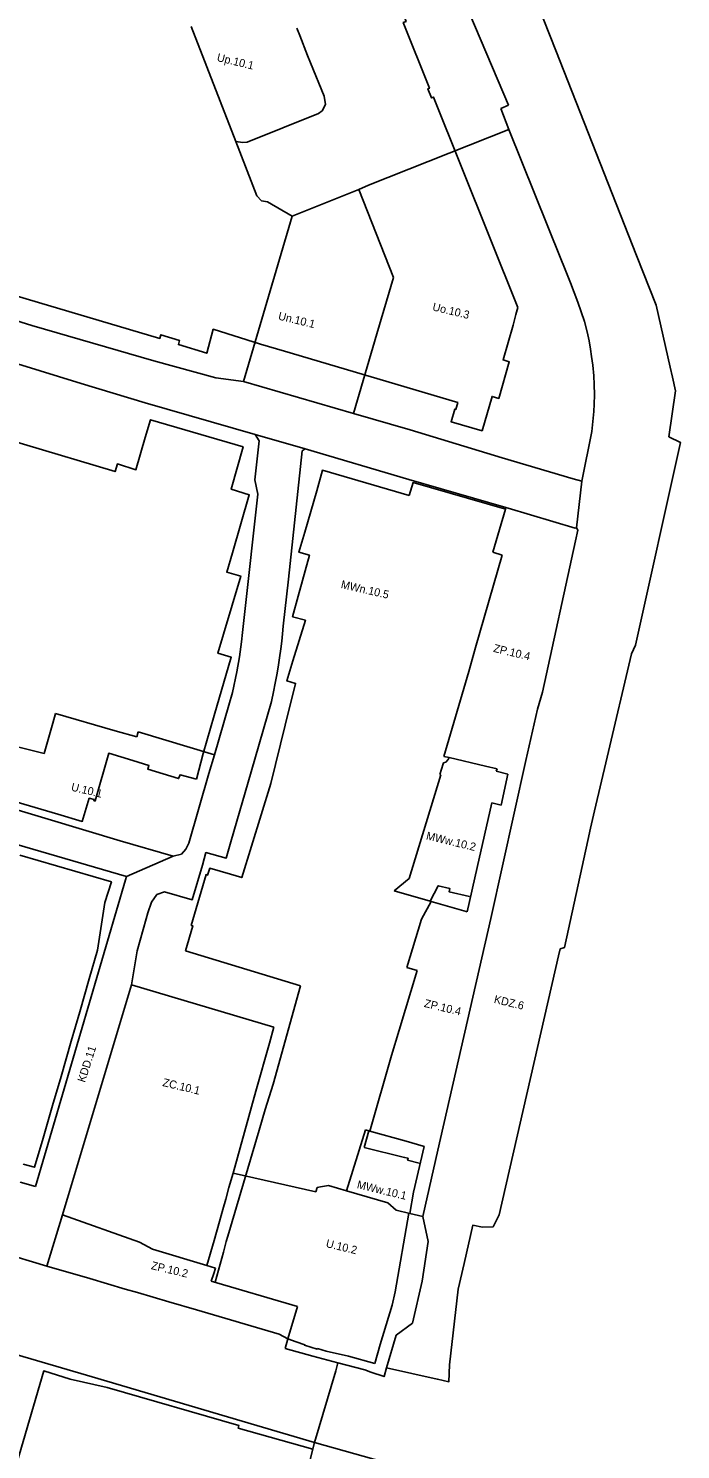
# Model space of a CAD drawing. Extents: x 7429686 to 7432896, y 5547954 to 5550600.
# Drawn here: x 7431990 to 7432316, y 5548459 to 5549170 of the extents above; entities that cross this region are included whole.
import ezdxf

# ---------------------------------------------------------------- set-up
doc = ezdxf.new("R2010")
doc.units = 0
for name, color, linetype in [('granica planu', 7, 'Continuous'), ('linie rozgraniczające', 7, 'Continuous'), ('nieprzekraczalna linia zabudowy', 7, 'Continuous'), ('obowiązująca linia zabudowy', 7, 'Continuous'), ('oznaczenia przeznaczeń', 7, 'Continuous')]:
    doc.layers.add(name, color=color, linetype=linetype)

msp = doc.modelspace()

# ---------------------------------------------------------------- linework, layer by layer
at = {"layer": 'granica planu'}
for points in [[(7432203.11, 5549285.85), (7432253.35, 5549158.49), (7432293.8, 5549055.97), (7432303.59, 5549031.15), (7432310.64, 5549000.22), (7432311.77, 5548995.18), (7432313.3, 5548988.36), (7432309.98, 5548965.44), (7432315.78, 5548962.55), (7432293.25, 5548861.19), (7432291.27, 5548856.84), (7432279.1, 5548805.19), (7432272.8, 5548778.46), (7432270.7, 5548769.64), (7432269.38, 5548763.55), (7432257.74, 5548710.02), (7432255.6, 5548709.36), (7432254.81, 5548705.91), (7432225.08, 5548576.47), (7432222.05, 5548570.38), (7432216.81, 5548570.26), (7432211.93, 5548571.17), (7432207.55, 5548552.09), (7432204.59, 5548539.19), (7432200.26, 5548501.41), (7432200, 5548492.94)], [(7432200, 5548492.94), (7432194.33, 5548494.21), (7432194.14, 5548494.25), (7432168.86, 5548499.89), (7432167.55, 5548495.53), (7432161.04, 5548497.78), (7432158.03, 5548498.87), (7432144.51, 5548502.39), (7432143.43, 5548498.33), (7432132.81, 5548462.54), (7432162.54, 5548454.18), (7432165.08, 5548453.77), (7432164.94, 5548451.89), (7432168.88, 5548447.76), (7432167.65, 5548438.77), (7432180.47, 5548435.15), (7432182.05, 5548445.83)]]:
    msp.add_lwpolyline(points, dxfattribs=at)
at = {"layer": 'linie rozgraniczające'}
for points in [[(7432168.86, 5548499.89), (7432194.14, 5548494.25), (7432194.33, 5548494.21), (7432200, 5548492.94), (7432200.26, 5548501.41), (7432204.59, 5548539.19), (7432207.55, 5548552.09), (7432211.93, 5548571.17), (7432216.81, 5548570.26), (7432222.05, 5548570.38), (7432225.08, 5548576.47), (7432254.81, 5548705.91), (7432255.6, 5548709.36), (7432257.74, 5548710.02), (7432269.38, 5548763.55), (7432270.7, 5548769.64), (7432272.8, 5548778.46), (7432279.1, 5548805.19), (7432291.27, 5548856.84), (7432293.25, 5548861.19), (7432315.78, 5548962.55), (7432309.98, 5548965.44), (7432313.3, 5548988.36), (7432311.77, 5548995.18), (7432310.64, 5549000.22), (7432303.59, 5549031.15), (7432293.8, 5549055.97), (7432253.35, 5549158.49), (7432203.11, 5549285.85)], [(7432229.83, 5549131.2), (7432207.69, 5549183.3)], [(7432093.48, 5549113.01), (7432071.12, 5549170.55)], [(7432124.05, 5549169.74), (7432125.48, 5549166.09)], [(7432125.48, 5549166.09), (7432129.3, 5549156.12)], [(7432129.3, 5549156.12), (7432130.75, 5549152.41)], [(7432130.75, 5549152.41), (7432137.69, 5549135.71)], [(7432137.69, 5549135.71), (7432138.38, 5549131.58)], [(7432134.86, 5549126.97), (7432099.15, 5549112.79)], [(7432136.66, 5549128.33), (7432134.86, 5549126.97)], [(7432138.38, 5549131.58), (7432136.66, 5549128.33)], [(7432225.87, 5549129.6), (7432229.83, 5549131.2)], [(7432230.02, 5549119.08), (7432225.87, 5549129.6)], [(7432159.78, 5549091.18), (7432230.02, 5549119.08)], [(7432255.91, 5549054.43), (7432230.02, 5549119.08)], [(7432104.03, 5549085.85), (7432093.48, 5549113.01)], [(7432096.91, 5549112.48), (7432093.48, 5549113.01)], [(7432099.15, 5549112.79), (7432096.91, 5549112.48)], [(7432154.96, 5549089.12), (7432159.78, 5549091.18)], [(7432106.29, 5549083.34), (7432104.03, 5549085.85)], [(7432109.26, 5549082.81), (7432106.29, 5549083.34)], [(7432121.67, 5549075.7), (7432109.26, 5549082.81)], [(7432121.67, 5549075.7), (7432154.96, 5549089.12)], [(7432172.23, 5549045.13), (7432154.96, 5549089.12)], [(7432108.98, 5549032.73), (7432121.67, 5549075.7)], [(7432257.76, 5549049.82), (7432255.91, 5549054.43)], [(7432260.77, 5549042.31), (7432257.76, 5549049.82)], [(7432164, 5549016.82), (7432172.23, 5549045.13)], [(7432264.5, 5549032.64), (7432260.77, 5549042.31)], [(7431991.53, 5549021.11), (7431973.2, 5549026.64)], [(7432097.35, 5548993.11), (7432108.98, 5549032.73)], [(7432267.76, 5549023.05), (7432264.5, 5549032.64)], [(7432052.51, 5549003.41), (7431991.53, 5549021.11)], [(7432269.08, 5549017.85), (7432267.76, 5549023.05)], [(7432152.22, 5548977.04), (7432164, 5549016.82)], [(7432270.06, 5549013.43), (7432269.08, 5549017.85)], [(7432270.84, 5549009.14), (7432270.06, 5549013.43)], [(7432271.31, 5549005.52), (7432270.84, 5549009.14)], [(7432271.9, 5549001.19), (7432271.31, 5549005.52)], [(7431984.36, 5549001.84), (7432016.11, 5548992.11)], [(7432083.44, 5548994.94), (7432052.51, 5549003.41)], [(7432272.37, 5548995.94), (7432271.9, 5549001.19)], [(7432016.11, 5548992.11), (7432048.11, 5548982.42)], [(7432097.35, 5548993.11), (7432083.44, 5548994.94)], [(7432152.22, 5548977.04), (7432097.35, 5548993.11)], [(7432272.66, 5548991.47), (7432272.37, 5548995.94)], [(7432272.75, 5548986.4), (7432272.66, 5548991.47)], [(7432272.66, 5548981.78), (7432272.75, 5548986.4)], [(7432048.11, 5548982.42), (7432103.12, 5548966.63)], [(7432180.66, 5548968.86), (7432152.22, 5548977.04)], [(7432271.91, 5548973.09), (7432272.39, 5548978.03)], [(7432272.39, 5548978.03), (7432272.66, 5548981.78)], [(7432271.47, 5548968.1), (7432271.91, 5548973.09)], [(7432103.01, 5548943.88), (7432105.13, 5548963.38)], [(7432103.12, 5548966.63), (7432128.2, 5548959.36)], [(7432105.13, 5548963.38), (7432103.12, 5548966.63)], [(7432226.68, 5548954.9), (7432180.66, 5548968.86)], [(7432266.39, 5548943.16), (7432271.47, 5548968.1)], [(7432128.2, 5548959.36), (7432126.61, 5548958.33), (7432119.75, 5548894.25), (7432117.22, 5548870.67), (7432116.81, 5548866.89), (7432116.44, 5548863.14), (7432116.01, 5548859.37), (7432115.37, 5548854.86), (7432114.64, 5548850.29), (7432113.97, 5548846.38), (7432113.21, 5548842.27), (7432112.27, 5548837.86), (7432111.24, 5548833.11), (7432101.1, 5548797.96), (7432090.96, 5548762.83), (7432088.73, 5548754.77), (7432078.54, 5548757.51), (7432076.77, 5548751.25), (7432071.7, 5548733.94), (7432057.91, 5548737.91), (7432054.07, 5548736.6), (7432051.26, 5548732.71), (7432049.55, 5548727.35), (7432048.68, 5548724.33), (7432044.15, 5548708.4), (7432041.39, 5548691.31)], [(7432128.2, 5548959.36), (7432179.92, 5548944.13)], [(7432262.04, 5548944.46), (7432226.68, 5548954.9)], [(7432104.41, 5548936.74), (7432103.01, 5548943.88)], [(7432179.92, 5548944.13), (7432228.44, 5548930.02)], [(7432266.39, 5548943.16), (7432262.04, 5548944.46)], [(7432263.68, 5548919.85), (7432266.39, 5548943.16)], [(7432097.86, 5548876.55), (7432104.41, 5548936.74)], [(7432225.27, 5548919.02), (7432228.21, 5548929.2)], [(7432228.21, 5548929.2), (7432228.44, 5548930.02)], [(7432228.44, 5548930.02), (7432229.57, 5548929.69)], [(7432229.57, 5548929.69), (7432263.04, 5548919.68)], [(7432263.04, 5548919.68), (7432263.68, 5548919.85)], [(7432264.44, 5548918.78), (7432263.68, 5548919.85)], [(7432221.99, 5548907.67), (7432225.27, 5548919.02)], [(7432246.79, 5548837.75), (7432263.3, 5548913.34)], [(7432263.3, 5548913.34), (7432264.44, 5548918.78)], [(7432213.35, 5548860.03), (7432226.56, 5548906.19)], [(7432226.56, 5548906.19), (7432221.99, 5548907.67)], [(7432096.88, 5548867.48), (7432097.36, 5548872.04)], [(7432097.36, 5548872.04), (7432097.86, 5548876.55)], [(7432095.31, 5548855.46), (7432096.35, 5548862.95)], [(7432096.35, 5548862.95), (7432096.88, 5548867.48)], [(7432093.97, 5548847.96), (7432095.31, 5548855.46)], [(7432209.94, 5548847.99), (7432213.35, 5548860.03)], [(7432091.75, 5548837.62), (7432093.97, 5548847.96)], [(7432197.42, 5548805.62), (7432209.94, 5548847.99)], [(7432089.92, 5548831.17), (7432091.75, 5548837.62)], [(7432244.25, 5548829.15), (7432246.79, 5548837.75)], [(7432001.98, 5548822.29), (7432003.3, 5548827.01)], [(7432003.3, 5548827.01), (7432033.19, 5548818.44)], [(7432082.76, 5548806.4), (7432089.92, 5548831.17)], [(7432238.52, 5548803.54), (7432244.25, 5548829.15)], [(7431997.73, 5548807.08), (7432001.98, 5548822.29)], [(7432033.19, 5548818.44), (7432043.93, 5548815.36)], [(7432043.93, 5548815.36), (7432044.73, 5548817.94)], [(7432044.73, 5548817.94), (7432082.76, 5548806.4)], [(7431975.55, 5548812.55), (7431997.73, 5548807.08)], [(7432080.07, 5548797.11), (7432082.76, 5548806.4)], [(7432195.53, 5548796.54), (7432197.11, 5548801.86)], [(7432197.11, 5548801.86), (7432197.28, 5548802.42)], [(7432197.28, 5548802.42), (7432198.4, 5548802.75)], [(7432200.09, 5548804.99), (7432197.42, 5548805.62)], [(7432198.4, 5548802.75), (7432199.56, 5548804.09)], [(7432199.56, 5548804.09), (7432200.09, 5548804.99)], [(7432200.09, 5548804.99), (7432218.3, 5548800.73)], [(7432218.3, 5548800.73), (7432224.05, 5548799.38)], [(7432220.89, 5548724.61), (7432238.52, 5548803.54)], [(7432224.05, 5548799.38), (7432223.64, 5548798.16)], [(7432070.01, 5548762.28), (7432080.07, 5548797.11)], [(7432180.1, 5548744.56), (7432196.02, 5548796.32)], [(7432196.02, 5548796.32), (7432195.53, 5548796.54)], [(7432223.64, 5548798.16), (7432229.5, 5548796.65)], [(7432229.5, 5548796.65), (7432226.09, 5548781.25)], [(7431999.67, 5548774.22), (7431976.39, 5548781.2)], [(7432221.39, 5548782.39), (7432214.13, 5548750.13)], [(7432226.09, 5548781.25), (7432221.39, 5548782.39)], [(7432035.61, 5548763.38), (7431999.67, 5548774.22)], [(7431956.98, 5548769.32), (7432038.88, 5548745.56)], [(7432062.13, 5548755.64), (7432035.61, 5548763.38)], [(7432062.13, 5548755.64), (7432066.29, 5548756.79)], [(7432066.29, 5548756.79), (7432068.49, 5548759.22)], [(7432068.49, 5548759.22), (7432070.01, 5548762.28)], [(7432038.88, 5548745.56), (7432062.13, 5548755.64)], [(7432214.13, 5548750.13), (7432209.14, 5548727.97)], [(7431993.32, 5548590.62), (7432038.42, 5548743.82)], [(7432038.42, 5548743.82), (7432038.88, 5548745.56)], [(7432172.62, 5548738.42), (7432180.1, 5548744.56)], [(7432190.62, 5548733.27), (7432172.62, 5548738.42)], [(7432186.33, 5548724.17), (7432191.11, 5548733.13)], [(7432191.11, 5548733.13), (7432190.62, 5548733.27)], [(7432208.66, 5548728.11), (7432191.11, 5548733.13)], [(7432209.14, 5548727.97), (7432208.66, 5548728.11)], [(7432178.9, 5548700.04), (7432186.33, 5548724.17)], [(7432194.52, 5548608.66), (7432220.89, 5548724.61)], [(7432184.06, 5548698.54), (7432178.9, 5548700.04)], [(7432175.12, 5548668.7), (7432184.06, 5548698.54)], [(7432006.79, 5548576.4), (7432041.39, 5548691.31)], [(7432041.39, 5548691.31), (7432112.49, 5548670.18)], [(7432112.49, 5548670.18), (7432110.25, 5548662.18)], [(7432171.27, 5548656.09), (7432175.12, 5548668.7)], [(7432110.25, 5548662.18), (7432103.55, 5548638.23)], [(7432160.47, 5548618.3), (7432171.27, 5548656.09)], [(7432103.55, 5548638.23), (7432092.1, 5548597.3)], [(7432148.75, 5548588.41), (7432158.33, 5548618.9)], [(7432158.33, 5548618.9), (7432159.99, 5548618.43)], [(7432159.99, 5548618.43), (7432160.47, 5548618.3)], [(7432178.6, 5548613.17), (7432160.47, 5548618.3)], [(7432187.19, 5548610.74), (7432178.6, 5548613.17)], [(7432182.3, 5548587.67), (7432187.67, 5548610.6)], [(7432187.01, 5548575.61), (7432194.52, 5548608.66)], [(7432187.67, 5548610.6), (7432187.19, 5548610.74)], [(7431985.71, 5548592.71), (7431993.32, 5548590.62)], [(7432090.06, 5548590.02), (7432092.1, 5548597.3)], [(7432092.1, 5548597.3), (7432133.45, 5548587.85)], [(7432088.44, 5548584.25), (7432090.06, 5548590.02)], [(7432133.45, 5548587.85), (7432134.13, 5548590.12)], [(7432134.13, 5548590.12), (7432135.85, 5548590.39)], [(7432135.85, 5548590.39), (7432139.75, 5548591)], [(7432139.75, 5548591), (7432148.75, 5548588.41)], [(7432169.46, 5548582.44), (7432148.75, 5548588.41)], [(7432180.46, 5548577.11), (7432182.3, 5548587.67)], [(7432085.28, 5548573.02), (7432086.99, 5548579.09)], [(7432086.99, 5548579.09), (7432088.44, 5548584.25)], [(7432173.65, 5548578.66), (7432169.46, 5548582.44)], [(7432180.46, 5548577.11), (7432173.65, 5548578.66)], [(7431999.07, 5548550.77), (7432006.79, 5548576.4)], [(7432045.4, 5548562.65), (7432006.79, 5548576.4)], [(7432082.61, 5548563.57), (7432085.28, 5548573.02)], [(7432187.01, 5548575.61), (7432180.46, 5548577.11)], [(7432189.55, 5548563.05), (7432187.01, 5548575.61)], [(7432051.83, 5548559.23), (7432045.4, 5548562.65)], [(7432079.07, 5548551.02), (7432051.83, 5548559.23)], [(7432079.07, 5548551.02), (7432082.61, 5548563.57)], [(7432186.55, 5548543.3), (7432189.55, 5548563.05)], [(7431991.83, 5548552.89), (7431982.95, 5548555.5)], [(7431999.07, 5548550.77), (7431991.83, 5548552.89)], [(7432020.43, 5548544.5), (7431999.07, 5548550.77)], [(7432083.28, 5548549.77), (7432079.07, 5548551.02)], [(7432038.12, 5548539.31), (7432020.43, 5548544.5)], [(7432081.24, 5548543.23), (7432082.42, 5548547.02)], [(7432124.28, 5548530.56), (7432081.24, 5548543.23)], [(7432082.42, 5548547.02), (7432083.28, 5548549.77)], [(7432181.73, 5548522.26), (7432186.55, 5548543.3)], [(7432044.31, 5548537.48), (7432038.12, 5548539.31)], [(7432059.96, 5548532.84), (7432044.31, 5548537.48)], [(7432073.76, 5548528.91), (7432059.96, 5548532.84)], [(7432115.22, 5548516.71), (7432073.76, 5548528.91)], [(7432119.52, 5548514.32), (7432124.28, 5548530.56)], [(7432173.64, 5548516.25), (7432181.73, 5548522.26)], [(7432119.52, 5548514.32), (7432115.22, 5548516.71)], [(7432168.86, 5548499.89), (7432173.64, 5548516.25)], [(7431981.35, 5548507.31), (7432021.76, 5548495.37)], [(7432118.11, 5548509.49), (7432119.52, 5548514.32)], [(7432131.94, 5548505.67), (7432118.11, 5548509.49)], [(7432144.51, 5548502.39), (7432131.94, 5548505.67)], [(7432132.81, 5548462.54), (7432143.43, 5548498.33), (7432144.51, 5548502.39)], [(7432144.51, 5548502.39), (7432158.03, 5548498.87)], [(7432021.76, 5548495.37), (7432104.05, 5548471.04)], [(7432158.03, 5548498.87), (7432161.04, 5548497.78), (7432167.55, 5548495.53), (7432168.86, 5548499.89)], [(7432104.05, 5548471.04), (7432132.81, 5548462.54)], [(7432129.43, 5548449.47), (7432132.81, 5548462.54)], [(7432167.65, 5548438.77), (7432168.88, 5548447.76), (7432164.94, 5548451.89), (7432165.08, 5548453.77), (7432162.54, 5548454.18), (7432132.81, 5548462.54)]]:
    msp.add_lwpolyline(points, dxfattribs=at)
at = {"layer": 'nieprzekraczalna linia zabudowy'}
msp.add_line((7432068.32, 5548708.41), (7432125.85, 5548690.85), dxfattribs=at)
for points in [[(7432125.85, 5548690.85), (7432112.08, 5548641.67), (7432108.12, 5548629.07), (7432105.08, 5548618.74), (7432089.53, 5548565.76), (7432088.7, 5548563.02), (7432087.34, 5548557.69), (7432083.18, 5548542.66)], [(7432163, 5548502.04), (7432165.65, 5548511.6), (7432171.67, 5548531.24), (7432173.13, 5548537.92), (7432179.97, 5548577.22)]]:
    msp.add_lwpolyline(points, dxfattribs=at)
at = {"layer": 'obowiązująca linia zabudowy'}
msp.add_line((7432131.93, 5548459.15), (7432094.69, 5548469.76), dxfattribs=at)
for points in [[(7432234.43, 5549030.05), (7432192.34, 5549135.26), (7432191.33, 5549134.86), (7432189.51, 5549139.4), (7432190.28, 5549139.71), (7432177.15, 5549172.52), (7432178.6, 5549173.1), (7432172.97, 5549187.19), (7432171.41, 5549186.57), (7432158.28, 5549219.39), (7432157.78, 5549219.2), (7432156, 5549223.65), (7432157.08, 5549224.08), (7432153.55, 5549232.89), (7432145.69, 5549229.75), (7432145.9, 5549229.24), (7432096.88, 5549209.63), (7432096.59, 5549210.34), (7432071.85, 5549200.44)], [(7431890.36, 5549063.02), (7431976.32, 5549038.08), (7431994.91, 5549032.49), (7432055.44, 5549014.62), (7432056.03, 5549016.4), (7432065.38, 5549013.54), (7432064.81, 5549011.51), (7432078.91, 5549007.17), (7432082.2, 5549019.17), (7432105.85, 5549011.75), (7432117.86, 5549008.18), (7432204.39, 5548982.49), (7432203.42, 5548979.11), (7432202.88, 5548979.27), (7432201.05, 5548972.89), (7432216.61, 5548968.41), (7432221.56, 5548985.6), (7432224.91, 5548984.63), (7432230.18, 5549002.93), (7432227.09, 5549003.82), (7432232.12, 5549021.29), (7432233.49, 5549026.51), (7432234.43, 5549030.05)], [(7432073.79, 5548794.14), (7432077.22, 5548807.01), (7432082.7, 5548826), (7432091.23, 5548855.14), (7432084.49, 5548857.14), (7432087.31, 5548866.67), (7432095.91, 5548895.72), (7432088.95, 5548897.74), (7432091.76, 5548907.42), (7432100.2, 5548936.45), (7432091.13, 5548939.15), (7432097.14, 5548960.46), (7432050.78, 5548973.93), (7432048.2, 5548965.02), (7432043.53, 5548948.94), (7432034.3, 5548951.81), (7432033.11, 5548947.97), (7431987.31, 5548961.78), (7431965.36, 5548968.4), (7431967.98, 5548977.35), (7431971, 5548987.66), (7431924.63, 5549001.26)], [(7432180.11, 5548935.98), (7432136.73, 5548948.66), (7432133.99, 5548938.39)], [(7432227.73, 5548929.34), (7432182.09, 5548942.54), (7432180.11, 5548935.98)], [(7432133.99, 5548938.39), (7432127.9, 5548917.69), (7432125, 5548907.67), (7432130.25, 5548906.21), (7432124.64, 5548885.66), (7432121.84, 5548875.43), (7432128.23, 5548873.69), (7432122.05, 5548853.44), (7432118.98, 5548843.36), (7432123.37, 5548842.07), (7432118.2, 5548821.3), (7432110.92, 5548792.04), (7432096.46, 5548745.05), (7432090.9, 5548746.66), (7432080.43, 5548749.7), (7432079.36, 5548746.27), (7432078.6, 5548746.49), (7432071.21, 5548721.13), (7432072, 5548720.84), (7432068.32, 5548708.41)], [(7431959.7, 5548789.91), (7431993.26, 5548780.1), (7432004.46, 5548776.66), (7432016.7, 5548773.07), (7432020.19, 5548784.68), (7432022.6, 5548784), (7432022.51, 5548783.46), (7432023.25, 5548783.37), (7432029.97, 5548807.17), (7432042.08, 5548803.49), (7432050.04, 5548801.08), (7432049.45, 5548799.14), (7432064.85, 5548794.5), (7432065.64, 5548796.4), (7432073.79, 5548794.14)], [(7431987.11, 5548601.81), (7431992.83, 5548600.15), (7431997.12, 5548614.72), (7432001.79, 5548631.07), (7432006.19, 5548645.64), (7432011.19, 5548663.25), (7432015.52, 5548677.84), (7432020.26, 5548694.38), (7432024.41, 5548708.77), (7432028.05, 5548732.5), (7432031.3, 5548742.89), (7431985.51, 5548756.24)], [(7432190.62, 5548733.27), (7432194.69, 5548740.91), (7432200.47, 5548739.55), (7432200.1, 5548737.91), (7432210.34, 5548735.59)], [(7432157.59, 5548610.05), (7432159.99, 5548618.43)], [(7432185.19, 5548602.2), (7432179.36, 5548603.65), (7432179.58, 5548604.68), (7432177.82, 5548605.11), (7432157.59, 5548610.05)], [(7432119.52, 5548514.32), (7432123.58, 5548512.87), (7432127.97, 5548511.4), (7432127.87, 5548511.17), (7432134.2, 5548509.23), (7432134.34, 5548509.53), (7432138.66, 5548508.23), (7432149.72, 5548505.72), (7432163, 5548502.04)], [(7432094.69, 5548469.76), (7432095.05, 5548471.04), (7432029.16, 5548490.11), (7432010.6, 5548494.29), (7431997.5, 5548498.35), (7431979.97, 5548438.57)]]:
    msp.add_lwpolyline(points, dxfattribs=at)

# ---------------------------------------------------------------- texts
at = {"layer": 'oznaczenia przeznaczeń'}
for s, rotation, p in [('Up.10.1', 346.4891, (7432083.75, 5549153.33)), ('Un.10.1', 346.4891, (7432114.4, 5549024.07)), ('Uo.10.3', 346.4891, (7432191.5, 5549028.65)), ('MWn.10.5', 347.06089, (7432145.74, 5548889.85)), ('ZP.10.4', 346.4891, (7432221.91, 5548857.94)), ('U.10.1', 346.4891, (7432010.88, 5548788.57)), ('MWw.10.2', 346.4891, (7432188.34, 5548764.16)), ('KDZ.6', 346.4891, (7432222.23, 5548682.43)), ('ZP.10.4', 346.4891, (7432187.33, 5548680.41)), ('KDD.11', 72.17427, (7432018.03, 5548642.29)), ('ZC.10.1', 346.4891, (7432056.59, 5548640.86)), ('MWw.10.1', 346.4891, (7432153.76, 5548589.78)), ('U.10.2', 346.4891, (7432138.24, 5548560.34)), ('ZP.10.2', 346.4891, (7432050.85, 5548549.31))]:
    msp.add_text(s, height=4, rotation=rotation, dxfattribs=at).set_placement(p)

doc.saveas('drawing.dxf')
